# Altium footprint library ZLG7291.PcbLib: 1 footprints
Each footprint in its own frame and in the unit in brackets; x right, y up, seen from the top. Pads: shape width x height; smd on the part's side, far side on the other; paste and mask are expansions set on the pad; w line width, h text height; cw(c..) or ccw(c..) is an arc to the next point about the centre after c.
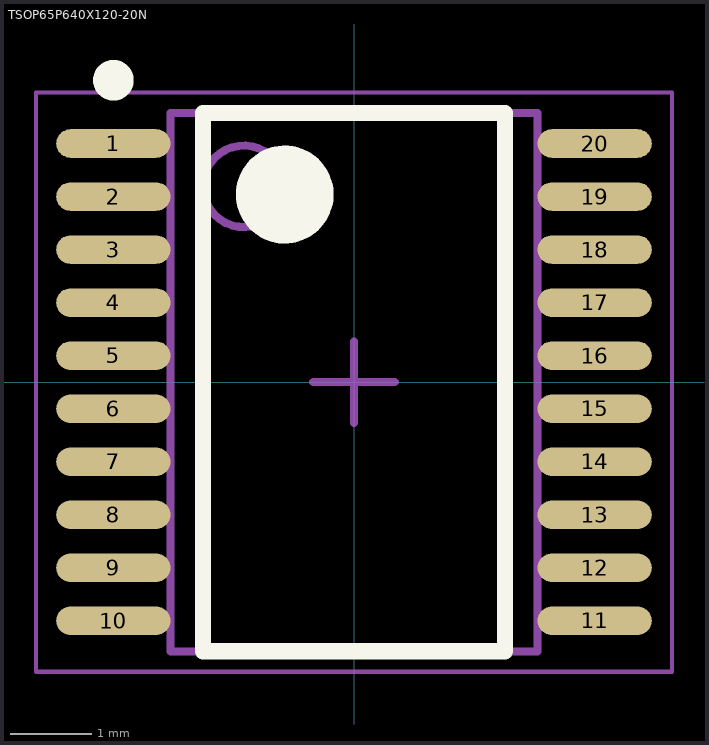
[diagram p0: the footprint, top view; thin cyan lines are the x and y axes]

## TSOP65P640X120-20N [mm] "TSOP, 20-Leads, Body 6.50x4.40mm, Pitch 0.65mm, IPC Medium Density,ZLGLIB"
height 1.2
pads (20):
  oval 1.4x0.35 smd: 1(-2.95,2.925) 2(-2.95,2.275) 3(-2.95,1.625) 4(-2.95,0.975) 5(-2.95,0.325) 6(-2.95,-0.325) 7(-2.95,-0.975) 8(-2.95,-1.625) 9(-2.95,-2.275) 10(-2.95,-2.925) 11(2.95,-2.925) 12(2.95,-2.275) 13(2.95,-1.625) 14(2.95,-0.975) 15(2.95,-0.325) 16(2.95,0.325) 17(2.95,0.975) 18(2.95,1.625) 19(2.95,2.275) 20(2.95,2.925)
Top Overlay:
  circle w0.25: c-2.95,3.7 r0.125
  circle w0.6: c-0.85,2.3 r0.3
  lines w0.2: -1.85,-3.3 -1.85,3.3 1.85,3.3 1.85,-3.3 -1.85,-3.3
Mechanical 13:
  circle w0.1: c-1.35,2.4 r0.5
  lines w0.1: -2.25,-3.3 -2.25,3.3 2.25,3.3 2.25,-3.3 -2.25,-3.3
Mechanical 15:
  lines w0.05: -3.9,-3.55 -3.9,3.55 3.9,3.55 3.9,-3.55 -3.9,-3.55
  lines w0.1: -0.5,0 0.5,0 ; 0,-0.5 0,0.5
3D body: height 1.2, standoff 0, extent -3.2,-3.3 3.2,3.3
